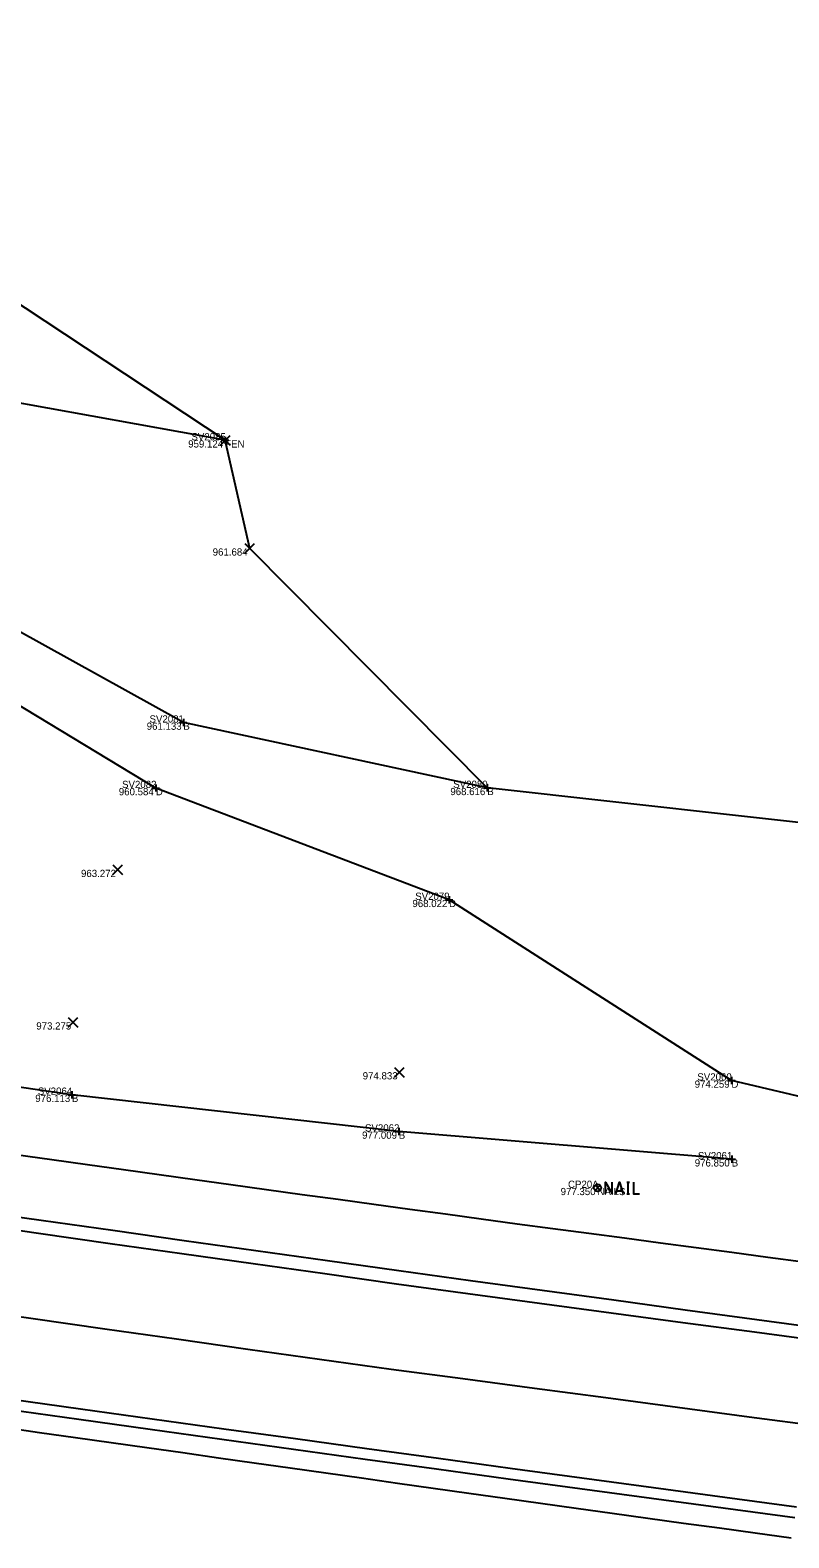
# Model space of a CAD drawing. Extents: x 2065431 to 2068157, y 709104 to 709719.
# Drawn here: x 2066480.2 to 2066585.2, y 709492.6 to 709701.2 of the extents above; entities that cross this region are included whole.
import ezdxf

# ---------------------------------------------------------------- set-up
doc = ezdxf.new("R2010")
doc.units = 0
for name, color, linetype in [('DT_X_Terrain_Boundary', 7, 'Continuous'), ('PM_X_Edge_Line', 7, 'Continuous'), ('PM_X_Lane_Line', 7, 'Continuous'), ('PV_X_EOP', 7, 'Continuous'), ('PV_X_Shoulder_Rumble_Strip', 7, 'Continuous'), ('RD_X_Fence', 7, 'Continuous'), ('RS_Raster1', 7, 'Continuous'), ('RW_X_CL_100_Bearings', 7, 'Continuous'), ('RW_X_CL_100_Stations', 7, 'Continuous'), ('RW_X_Fee_WL', 7, 'Continuous'), ('SV_X_Break_Lines', 7, 'Continuous'), ('SV_X_Mon_Cells_Found', 7, 'Continuous'), ('SV_X_Text_Elevation', 7, 'Continuous'), ('SV_X_Text_Name', 7, 'Continuous')]:
    doc.layers.add(name, color=color, linetype=linetype)

msp = doc.modelspace()

# ---------------------------------------------------------------- linework, layer by layer
at = {"layer": 'DT_X_Terrain_Boundary'}
msp.add_lwpolyline([(2066649.44, 709584.58), (2066543.44, 709596.37), (2066510.56, 709629.51), (2066507.17, 709644.46), (2066473.93, 709666.44), (2066463.59, 709680.71), (2066437.89, 709682.56), (2066422.56, 709690.18), (2066414.56, 709691.38), (2066359.14, 709688.04), (2066325.73, 709701.2), (2066327.01, 709677.48), (2066325.95, 709651.36), (2066268.91, 709598.56), (2066231.54, 709603.08), (2066151.93, 709594.95), (2066146.99, 709595.72), (2066142.05, 709596.5), (2066137.11, 709597.27), (2066132.17, 709598.05)], dxfattribs=at)
at = {"layer": 'PM_X_Edge_Line'}
for points in [[(2066471.45, 709536.18), (2066481.35, 709534.77), (2066491.25, 709533.36), (2066501.15, 709531.96), (2066511.05, 709530.56), (2066520.95, 709529.17), (2066530.86, 709527.78), (2066540.76, 709526.4), (2066550.67, 709525.07), (2066560.58, 709523.75), (2066570.5, 709522.43), (2066580.41, 709521.11), (2066590.32, 709519.79)], [(2066477.26, 709511.86), (2066487.16, 709510.47), (2066497.07, 709509.09), (2066506.97, 709507.71), (2066516.88, 709506.35), (2066526.78, 709504.98), (2066536.69, 709503.63), (2066546.6, 709502.27), (2066556.51, 709500.92), (2066566.42, 709499.57), (2066576.33, 709498.23), (2066586.24, 709496.89)]]:
    msp.add_lwpolyline(points, dxfattribs=at)
at = {"layer": 'PM_X_Lane_Line'}
msp.add_lwpolyline([(2066470.71, 709524.36), (2066480.61, 709522.95), (2066490.51, 709521.54), (2066500.41, 709520.13), (2066510.32, 709518.74), (2066520.22, 709517.34), (2066530.12, 709515.97), (2066540.04, 709514.65), (2066549.95, 709513.33), (2066559.86, 709512.01), (2066569.77, 709510.69), (2066579.69, 709509.37), (2066589.6, 709508.05)], dxfattribs=at)
at = {"layer": 'PV_X_EOP'}
for points in [[(2066478.22, 709545.66), (2066483.17, 709544.96), (2066488.13, 709544.27), (2066493.08, 709543.58), (2066498.03, 709542.89), (2066502.98, 709542.2), (2066507.93, 709541.51), (2066512.89, 709540.82), (2066517.84, 709540.14), (2066522.79, 709539.46), (2066527.75, 709538.78), (2066532.7, 709538.1), (2066537.65, 709537.42), (2066542.61, 709536.75), (2066547.56, 709536.08), (2066552.52, 709535.42), (2066557.48, 709534.76), (2066562.43, 709534.1), (2066567.39, 709533.44), (2066572.35, 709532.78), (2066577.3, 709532.12), (2066582.26, 709531.46), (2066587.21, 709530.8)], [(2066476.54, 709507.92), (2066481.49, 709507.21), (2066486.44, 709506.51), (2066491.39, 709505.8), (2066496.34, 709505.1), (2066501.29, 709504.4), (2066506.24, 709503.69), (2066511.19, 709502.99), (2066516.14, 709502.3), (2066521.1, 709501.6), (2066526.05, 709500.9), (2066531, 709500.2), (2066535.95, 709499.51), (2066540.9, 709498.81), (2066545.85, 709498.12), (2066550.8, 709497.42), (2066555.76, 709496.73), (2066560.71, 709496.04), (2066565.66, 709495.35), (2066570.61, 709494.66), (2066575.57, 709493.98), (2066580.52, 709493.3), (2066585.47, 709492.62)]]:
    msp.add_lwpolyline(points, dxfattribs=at)
at = {"layer": 'PV_X_Shoulder_Rumble_Strip'}
for points in [[(2066471.8, 709537.97), (2066481.7, 709536.56), (2066491.6, 709535.16), (2066501.5, 709533.77), (2066511.4, 709532.38), (2066521.31, 709530.99), (2066531.21, 709529.61), (2066541.12, 709528.24), (2066551.02, 709526.88), (2066560.93, 709525.53), (2066570.84, 709524.18), (2066580.75, 709522.83), (2066590.66, 709521.49)], [(2066477, 709510.43), (2066486.91, 709509.04), (2066496.81, 709507.65), (2066506.71, 709506.27), (2066516.62, 709504.89), (2066526.52, 709503.52), (2066536.43, 709502.15), (2066546.34, 709500.8), (2066556.25, 709499.45), (2066566.16, 709498.12), (2066576.07, 709496.78), (2066585.98, 709495.45)]]:
    msp.add_lwpolyline(points, dxfattribs=at)
at = {"layer": 'RD_X_Fence'}
msp.add_lwpolyline([(2066507.17, 709644.46), (2066476.5, 709650.02), (2066424.89, 709662.13), (2066402.33, 709666.52), (2066368.48, 709673.58)], dxfattribs=at)
at = {"layer": 'RS_Raster1'}
for p, q in [((2066506.67, 709644.46), (2066507.67, 709644.46)), ((2066507.17, 709644.96), (2066507.17, 709643.96)), ((2066507.17, 709644.46), (2066507.17, 709644.46)), ((2066501.38, 709605.91), (2066501.38, 709604.91)), ((2066500.88, 709605.41), (2066501.88, 709605.41)), ((2066501.38, 709605.41), (2066501.38, 709605.41)), ((2066497.07, 709596.35), (2066498.07, 709596.35)), ((2066497.57, 709596.85), (2066497.57, 709595.85)), ((2066497.57, 709596.35), (2066497.57, 709596.35)), ((2066542.94, 709596.37), (2066543.94, 709596.37)), ((2066543.44, 709596.87), (2066543.44, 709595.87)), ((2066543.44, 709596.37), (2066543.44, 709596.37)), ((2066537.65, 709580.88), (2066538.65, 709580.88)), ((2066538.15, 709581.38), (2066538.15, 709580.38)), ((2066538.15, 709580.88), (2066538.15, 709580.88)), ((2066576.72, 709555.89), (2066577.72, 709555.89)), ((2066577.22, 709556.39), (2066577.22, 709555.39)), ((2066577.22, 709555.89), (2066577.22, 709555.89)), ((2066485.46, 709553.92), (2066486.46, 709553.92)), ((2066485.96, 709554.42), (2066485.96, 709553.42)), ((2066485.96, 709553.92), (2066485.96, 709553.92)), ((2066530.69, 709548.83), (2066531.69, 709548.83)), ((2066531.19, 709549.33), (2066531.19, 709548.33)), ((2066531.19, 709548.83), (2066531.19, 709548.83)), ((2066577.27, 709545.49), (2066577.27, 709544.49)), ((2066576.77, 709544.99), (2066577.77, 709544.99)), ((2066577.27, 709544.99), (2066577.27, 709544.99))]:
    msp.add_line(p, q, dxfattribs=at)
at = {"layer": 'RW_X_CL_100_Bearings'}
for p, q in [((2066506.51, 709643.79), (2066507.84, 709645.13)), ((2066506.51, 709645.13), (2066507.84, 709643.79)), ((2066509.9, 709628.84), (2066511.23, 709630.17)), ((2066509.9, 709630.17), (2066511.23, 709628.84)), ((2066491.62, 709584.37), (2066492.96, 709585.71)), ((2066491.62, 709585.71), (2066492.96, 709584.37)), ((2066485.43, 709563.27), (2066486.77, 709564.61)), ((2066485.43, 709564.61), (2066486.77, 709563.27)), ((2066530.6, 709556.37), (2066531.93, 709557.71)), ((2066530.6, 709557.71), (2066531.93, 709556.37))]:
    msp.add_line(p, q, dxfattribs=at)
at = {"layer": 'RW_X_CL_100_Stations'}
for p, q in [((2066558.35, 709541.39), (2066559.06, 709540.68)), ((2066558.35, 709540.68), (2066559.06, 709541.39))]:
    msp.add_line(p, q, dxfattribs=at)
for points in [[(2066559.79, 709540.22), (2066559.79, 709541.82), (2066560.74, 709540.22), (2066560.74, 709541.82)], [(2066561.24, 709540.22), (2066561.75, 709541.82), (2066562.24, 709540.22)], [(2066562.74, 709541.82), (2066563.14, 709541.82)], [(2066562.94, 709540.22), (2066562.94, 709541.82)], [(2066563.65, 709541.82), (2066563.65, 709540.22), (2066564.52, 709540.22)], [(2066562.11, 709540.6), (2066561.37, 709540.6)], [(2066562.74, 709540.22), (2066563.14, 709540.22)]]:
    msp.add_lwpolyline(points, dxfattribs=at)
msp.add_circle((2066558.7, 709541.03), 0.5, dxfattribs=at)
at = {"layer": 'RW_X_Fee_WL'}
msp.add_lwpolyline([(2066834.34, 709517.99), (2066792.15, 709523.14), (2066747.37, 709529.6), (2066701.7, 709535.47), (2066656.28, 709541.34), (2066614.98, 709547.01), (2066577.22, 709555.89), (2066538.15, 709580.88), (2066497.57, 709596.35), (2066445.11, 709628.08), (2066445.1, 709628.08), (2066425.53, 709638.57), (2066410.9, 709640.69), (2066399.97, 709646.12), (2066394.4, 709644.52), (2066392.47, 709644.49), (2066393.15, 709634.42)], dxfattribs=at)
at = {"layer": 'SV_X_Break_Lines'}
for points in [[(2066543.44, 709596.37), (2066501.38, 709605.41), (2066446.93, 709635.56), (2066446.96, 709635.6)], [(2066577.27, 709544.99), (2066531.19, 709548.83), (2066485.96, 709553.92), (2066443.13, 709560.12), (2066391.19, 709568.7), (2066356.03, 709572.66), (2066312.45, 709579.16), (2066268.38, 709586.52), (2066230.11, 709591.56)]]:
    msp.add_lwpolyline(points, dxfattribs=at)

# ---------------------------------------------------------------- texts
at = {"layer": 'SV_X_Mon_Cells_Found'}
for s, p in [('SV2085', (2066502.5, 709644.46)), ('SV2081', (2066496.7, 709605.41)), ('SV2082', (2066492.9, 709596.35)), ('SV2080', (2066538.73, 709596.37)), ('SV2079', (2066533.47, 709580.88)), ('SV2060', (2066572.51, 709555.89)), ('SV2064', (2066481.24, 709553.92)), ('SV2062', (2066526.52, 709548.83)), ('SV2061', (2066572.59, 709544.99)), ('CP20A', (2066554.61, 709541.03))]:
    msp.add_text(s, height=1, dxfattribs=at).set_placement(p)
at = {"layer": 'SV_X_Text_Elevation'}
for s, p in [('FEN', (2066507.17, 709643.46)), ('B', (2066501.38, 709604.41)), ('D', (2066497.57, 709595.35)), ('B', (2066543.44, 709595.37)), ('D', (2066538.15, 709579.88)), ('D', (2066577.22, 709554.89)), ('B', (2066485.96, 709552.92)), ('B', (2066531.19, 709547.83)), ('B', (2066577.27, 709543.99)), ('NAILS', (2066558.7, 709540.03))]:
    msp.add_text(s, height=1, dxfattribs=at).set_placement(p)
at = {"layer": 'SV_X_Text_Name'}
for s, p in [('959.124', (2066502.05, 709643.46)), ('959.124', (2066502.05, 709643.46)), ('961.684', (2066505.44, 709628.51)), ('961.133', (2066496.31, 709604.41)), ('960.584', (2066492.45, 709595.35)), ('968.616', (2066538.33, 709595.37)), ('963.272', (2066487.22, 709584.04)), ('968.022', (2066533.08, 709579.88)), ('973.275', (2066481.03, 709562.94)), ('974.833', (2066526.2, 709556.04)), ('974.259', (2066572.14, 709554.89)), ('976.113', (2066480.89, 709552.92)), ('977.009', (2066526.11, 709547.83)), ('976.850', (2066572.15, 709543.99)), ('977.350', (2066553.59, 709540.03))]:
    msp.add_text(s, height=1, dxfattribs=at).set_placement(p)

doc.saveas('drawing.dxf')
